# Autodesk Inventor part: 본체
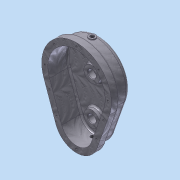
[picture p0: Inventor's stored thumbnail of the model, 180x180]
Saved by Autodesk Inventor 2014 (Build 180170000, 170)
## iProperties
Created: 2024-05
Part Number: 본체
Material: 알루미늄 6061, 용접
Document SubType Name: Modeling
Designer: dg
Density: 2.71 g/cm^3
Appearance: 용접 - 알루미늄
Mass: 506.304 g
Surface Area: 652.283 cm^2
Volume: 186.828 cm^3
Author: dg
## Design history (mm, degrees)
sketch "스케치1"
  geometry: L1 (-58.454, 14.548)-(-36.77, -46.785); L2 (0, 97.215)-(0, -72.785); L3 (58.454, 14.548)-(36.77, -46.785); A1 r 62 centre (0, 35.215) between (58.454, 14.548) and (-58.454, 14.548); A2 r 39 centre (0, -33.785) between (-36.77, -46.785) and (36.77, -46.785); 1 further point
  constraints: 6 end point, 6 point on circle, 2 centre point, 2 symmetric about line, 2 tangent, 2 vertical alignment, 1 vertical
  dimensions: "d0" = 124 diameter of A1; "d2" = 69 distance of A2.centre A1.centre; "d3" = 39 radius of A2
extrude "돌출1" new body sketch "스케치1" distance "d4" = 15; taper "d5" = 0 deg
sketch "스케치2"
  geometry: L1 (-36.77, 46.785)-(-58.454, -14.548) reference; L2 (-31.113, 44.785)-(-53.682, -19.052); L3 (0, 72.785)-(0, -97.215); L4 (31.113, 44.785)-(53.682, -19.052); A1 r 39 centre (0, 33.785) between (36.77, 46.785) and (-36.77, 46.785) reference; A2 r 62 centre (0, -35.215) between (-58.454, -14.548) and (58.454, -14.548) reference; A3 r 56 centre (0, -35.215) between (-52.797, -16.548) and (52.797, -16.548); A4 r 33 centre (0, 33.785) between (31.113, 44.785) and (-31.113, 44.785); 1 further point
  constraints: 6 end point, 6 point on circle, 2 centre point, 2 coincident, 2 point on line, 2 symmetric about line, 2 tangent, 1 parallel
  dimensions: "d6" = 112 diameter of A3; "d7" = 66 diameter of A4
extrude "돌출2" join sketch "스케치2" distance "d8" = 25; taper "d9" = 0 deg
feature "쉘1" dims "d10" = 5
sketch "스케치3"
  geometry: L1 (26.399, -78.333)-(48.083, -17) reference; L2 (53.74, -19)-(32.056, -80.333) reference; L3 (-32.056, -80.333)-(-53.74, -19) reference; L4 (53.74, -19)-(32.056, -80.333) reference; L5 (-48.083, -17)-(-26.399, -78.333); L6 (48.083, -17)-(26.399, -78.333); L7 (48.083, -17)-(26.399, -78.333) reference; L8 (53.74, -19)-(32.056, -80.333); L9 (58.454, -20.667)-(36.77, -82) reference; L10 (-53.74, -19)-(-32.056, -80.333); A1 r 28 centre (0, -69) between (-26.399, -78.333) and (26.399, -78.333) reference; A2 r 51 centre (0, 0) between (48.083, -17) and (-48.083, -17) reference; A3 r 57 centre (0, 0) between (53.74, -19) and (-53.74, -19) reference; A4 r 34 centre (0, -69) between (-32.056, -80.333) and (32.056, -80.333) reference; A5 r 57 centre (0, 0) between (53.74, -19) and (-53.74, -19) reference; A6 r 34 centre (0, -69) between (-32.056, -80.333) and (32.056, -80.333) reference; A7 r 28 centre (0, -69) between (-26.399, -78.333) and (26.399, -78.333); A8 r 57 centre (0, 0) between (53.74, -19) and (-53.74, -19); A9 r 34 centre (0, -69) between (-32.056, -80.333) and (32.056, -80.333); A10 r 51 centre (0, 0) between (48.083, -17) and (-48.083, -17); 1 further point
  constraints: 20 tangent, 10 end point, 9 point on circle, 4 centre point, 4 coincident, 4 equal length, 3 point on line
extrude "돌출3" join sketch "스케치3" stored distance "d11" = 25; taper "d12" = 0 deg
sketch "스케치4"
  geometry: A1 r 51 centre (0, 35.215) between (48.083, 18.215) and (-48.083, 18.215) reference; 2 further points
  constraints: 1 vertical alignment
  dimensions: "d13" = 56 distance of A1.centre point (0, 91.215)
hole "구멍1" sketch "스케치4" at (0, 91.215) diameter "d14" = 3.242; stored, may be unused: countersink angle "d18" = 90 deg, drill point angle "d20" = 118 deg; dims "d15" = 8, "d16" = 4, "d17" = 2, "d19" = 10
sketch "스케치5"
  geometry: L1 (-36.77, -46.785)-(-58.454, 14.548) reference; L2 (-52.797, 16.548)-(-31.113, -44.785) reference; C1 r 1.621 at (-56, 35.215) reference; A1 r 33 centre (0, -33.785) between (-31.113, -44.785) and (31.113, -44.785) reference; 2 further points
  dimensions: "d24" = 69 vertical distance of point (-35.532, -33.785) C1.centre; "d25" = 5.5 distance from line of L1 point (-35.532, -33.785)
hole "구멍2" sketch "스케치5" at (-35.532, -33.785) diameter "d26" = 3.242; stored, may be unused: countersink angle "d30" = 90 deg, drill point angle "d32" = 118 deg; dims "d27" = 8, "d28" = 4, "d29" = 2, "d31" = 10
sketch "스케치6"
  geometry: L1 (-48.083, 18.215)-(-26.399, -43.118) reference; C1 r 1.621 at (-56, 35.215) reference; 3 further points
  dimensions: "d33" = 34 vertical distance of C1.centre point (-47.906, 1.215); "d34" = 5.5 distance from line of L1 point (-47.906, 1.215)
hole "구멍3" sketch "스케치6" at (-47.906, 1.215) diameter "d35" = 3.242; stored, may be unused: countersink angle "d39" = 90 deg, drill point angle "d41" = 118 deg; dims "d36" = 8, "d37" = 4, "d38" = 2, "d40" = 10
sketch "스케치7"
  geometry: A1 r 39 centre (0, -33.785) between (-36.77, -46.785) and (36.77, -46.785) reference; 2 further points
  constraints: 1 vertical alignment
  dimensions: "d42" = 33 distance of A1.centre point (0, -66.785)
hole "구멍4" sketch "스케치7" at (0, -66.785) diameter "d43" = 3.242; stored, may be unused: countersink angle "d47" = 90 deg, drill point angle "d49" = 118 deg; dims "d44" = 8, "d45" = 4, "d46" = 2, "d48" = 10
sketch "스케치8"
  geometry: C1 r 14 at (0, 0); A1 r 51 centre (0, 0) between (48.083, -17) and (-48.083, -17) reference; 1 further point
  constraints: 1 centre point, 1 coincident
  dimensions: "d50" = 28 diameter of C1
extrude "돌출4" join sketch "스케치8" distance "d51" = 8; taper "d52" = 0 deg
sketch "스케치9"
  geometry: C1 r 15 at (0, -35.215); A1 r 56 centre (0, -35.215) between (-52.797, -16.548) and (52.797, -16.548) reference; 1 further point
  constraints: 1 centre point, 1 coincident
  dimensions: "d53" = 30 diameter of C1
extrude "돌출5" join sketch "스케치9" distance "d54" = 8; taper "d55" = 0 deg
sketch "스케치10"
  geometry: C1 r 14 at (0, -69); A1 r 28 centre (0, -69) between (-26.399, -78.333) and (26.399, -78.333) reference; 1 further point
  constraints: 1 centre point, 1 coincident
  dimensions: "d57" = 28 diameter of C1
extrude "돌출6" join sketch "스케치10" distance "d58" = 8; taper "d59" = 0 deg
sketch "스케치11"
  geometry: C1 r 14 at (0, 33.785) reference; C2 r 15 at (0, 33.785); 1 further point
  constraints: 1 centre point, 1 coincident
  dimensions: "d60" = 30 diameter of C2
extrude "돌출7" join sketch "스케치11" distance "d61" = 8; taper "d62" = 0 deg
hole "구멍5" diameter "d65" = 8; stored, may be unused: countersink angle "d69" = 90 deg, drill point angle "d71" = 120 deg; dims "d63" = 10, "d64" = 10, "d66" = 8, "d67" = 4, "d68" = 2, "d70" = 10
sketch "스케치12"
  geometry: C1 r 4 at (0, 0) reference; C2 r 14 at (0, 0) reference; C3 r 7 at (0, 0); 1 further point
  constraints: 1 centre point, 1 coincident
  dimensions: "d72" = 14 diameter of C3
extrude "돌출8" cut sketch "스케치12" distance "d73" = 10; taper "d74" = 0 deg
hole "구멍6" diameter "d77" = 14; stored, may be unused: countersink angle "d81" = 90 deg, drill point angle "d83" = 120 deg; dims "d75" = 10, "d76" = 10, "d78" = 8, "d79" = 20, "d80" = 4.2, "d82" = 10
chamfer "모따기1" distance "d84" = 1; stored, may be unused: second distance "d85" = 2, angle "d86" = 45 deg
chamfer "모따기2" distance "d87" = 0.1; stored, may be unused: second distance "d88" = 2, angle "d89" = 45 deg
chamfer "모따기3" distance "d90" = 0.4; stored, may be unused: second distance "d91" = 2, angle "d92" = 45 deg
fillet "모깎기1" dims "d93" = 3, "d94" = 8
fillet "모깎기2" dims "d95" = 3
node "작업 평면2"
node "작업 평면3"
sketch "스케치13"
  geometry: L1 (62, 0)-(-62, 0) reference; C1 r 6 at (0, 28); 4 further points
  constraints: 1 centre point, 1 midpoint, 1 vertical alignment
  dimensions: "d98" = 28 distance from line of C1.centre L1; "d99" = 12 diameter of C1
extrude "돌출9" join sketch "스케치13" stored distance "d100" = 10; taper "d101" = 0 deg
sketch "스케치14"
  geometry: C1 r 6 at (0, 28) reference; C2 r 6 at (0, 28); 1 further point
  constraints: 1 centre point, 1 coincident, 1 concentric
extrude "돌출10" join sketch "스케치14" stored distance "d102" = 10; taper "d103" = 0 deg
hole "구멍7" diameter "d106" = 6.188; stored, may be unused: countersink angle "d110" = 90 deg, drill point angle "d112" = 118 deg; dims "d107" = 20, "d108" = 7, "d109" = 2, "d111" = 8, "d126" = 10, "d127" = 10
hole "구멍8" diameter "d115" = 6.188; stored, may be unused: countersink angle "d119" = 90 deg, drill point angle "d121" = 118 deg; dims "d116" = 20, "d117" = 7, "d118" = 2, "d120" = 8, "d124" = 10, "d125" = 10
sketch "스케치15"
  geometry: C1 r 18 at (0, -35.215) reference; 2 further points
  constraints: 1 vertical alignment, 1 other
  dimensions: "d122" = 30 distance of C1.centre point (0, -65.215)
extrude "돌출11" join sketch "스케치15" distance "d123" = 0.5; taper "d128" = 0 deg
node "솔리드1"
pattern_circular "원형 패턴1" dims angle "d22" = 360 deg
mirror "대칭1"
node "투영된 루프1"
other parameters: "d1" = 78, "d96" = 93, "d97" = -71
